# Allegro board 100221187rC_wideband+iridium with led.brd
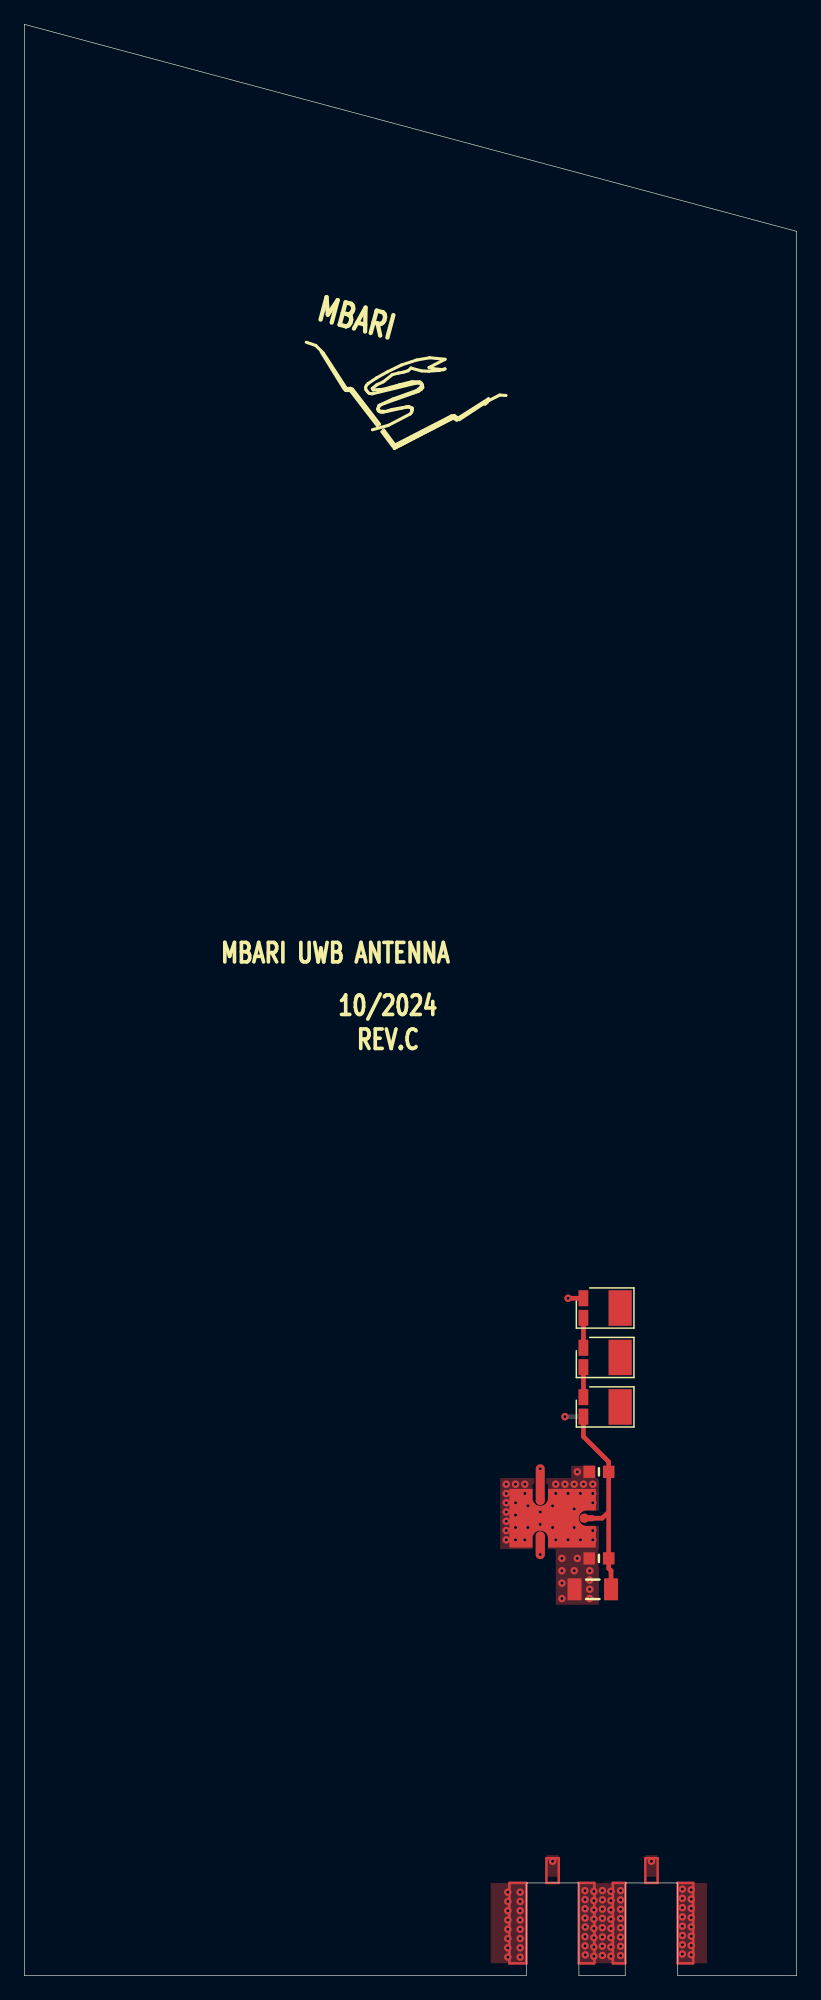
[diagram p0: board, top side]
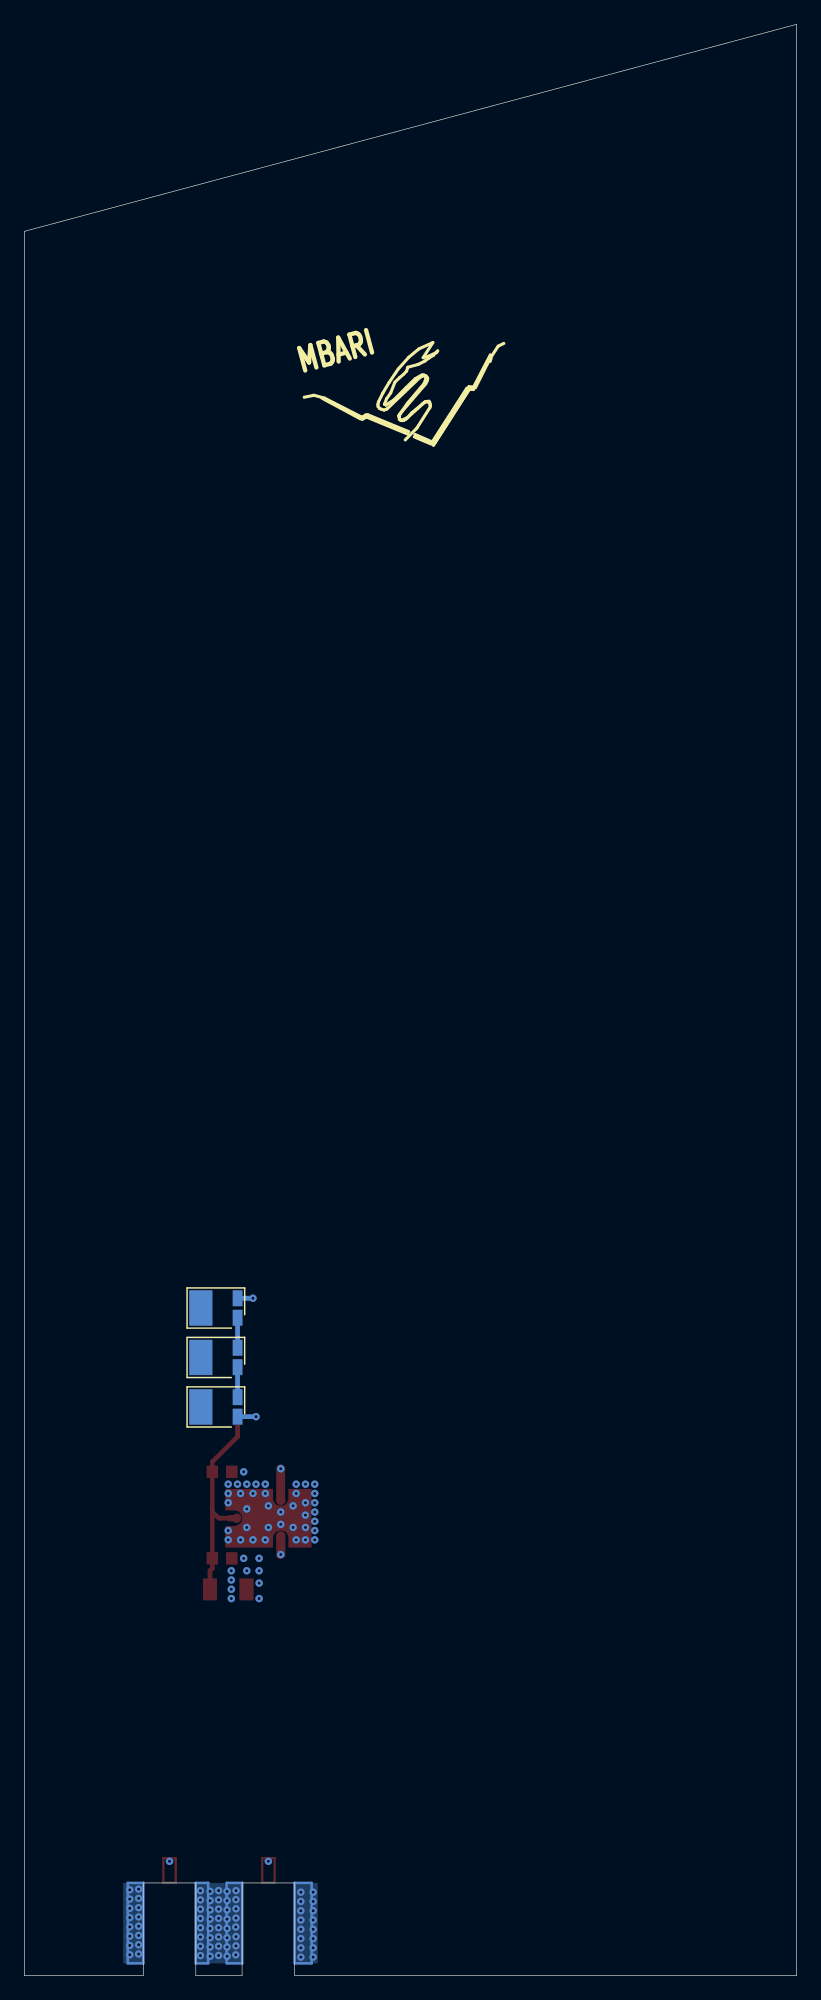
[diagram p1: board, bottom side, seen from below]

Outline 63.5 x 160.35 mm; copper layers: TOP, IN1, IN2, BOTTOM. Coordinates in mm from the lower left corner of the outline.
Outline path: 0,160.35 63.5,143.33 63.5,0 53.72,0 53.72,7.62 49.4,7.62 49.4,0 45.59,0 45.59,7.62 41.27,7.62 41.27,0 0,0 0,160.35

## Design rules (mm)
constraint set DEFAULT: min track width 0.127

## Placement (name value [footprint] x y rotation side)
C1  1.0uF  [CAPC3216X190N]  46.74 31.75 180 top
C2  10,000.0pF  [CAPC1608X87N]  47.24 41.4 180 top
C3  10,000.0pF  [CAPC1608X87N]  47.24 34.29 180 top
D1  LXM2-PH01-0070  [DIODFN449X305X210-3N]  47.75 46.74 0 top
D2  LXM2-PH01-0070  [DIODFN449X305X210-3N]  47.75 50.8 0 top
D3  LXM2-PH01-0070  [DIODFN449X305X210-3N]  47.75 54.86 0 top
D4  LXM2-PH01-0070  [DIODFN449X305X210-3N]  47.75 54.86 0 bottom
D5  LXM2-PH01-0070  [DIODFN449X305X210-3N]  47.75 50.8 0 bottom
D6  LXM2-PH01-0070  [DIODFN449X305X210-3N]  47.75 46.74 0 bottom
NOREF  -  []  -122.94 -69.6 0 top
NOREF#2  -  []  52.32 -0.64 0 top
NOREF#3  -  []  0 0 0 top
NOREF#4  -  []  41.27 0 0 top
NOREF#5  -  []  32.77 134.37 345 top
NOREF#6  -  []  -122.94 -69.6 0 top
NOREF#7  -  []  45.59 0 0 top
NOREF#8  -  []  79.76 11.43 0 top
NOREF#9  -  []  49.4 0 0 top
NOREF#10  -  []  63.5 0 90 top
NOREF#11  -  []  0 0 90 top
NOREF#12  -  []  0 160.35 0 top
NOREF#13  -  []  32.26 134.62 165 bottom
U1  BT-0014SMG  [MARKI_BTSM-PDSM]  43.43 37.59 0 top

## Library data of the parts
C1-C3 = CAP
D1-D6 = LED_C1A2
U1 = MARKI_BT-0014SMG-1

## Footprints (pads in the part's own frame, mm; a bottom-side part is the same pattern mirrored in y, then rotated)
CAPC1608X87N
  rect 0.95x1.001 smd: 1(-0.8,0) 2(0.8,0)
CAPC3216X190N
  rect 1.151x1.801 smd: 1(-1.501,0) 2(1.501,0)
DIODFN449X305X210-3N
  rect 1.89x2.901 smd: (1.234,0)
  rect 0.79x1.3 smd: 1(-1.786,0.8) 2(-1.786,-0.8)
MARKI_BTSM-PDSM
  custom 0.191x0.191 smd: 1(-1.016,-1.651) 2(-1.016,1.651) 3(2.794,0)
  custom 1.206x1.206 smd: 4(0,0)

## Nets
GND_SIGNAL: C1.2 C2.2 C3.2 D6.1(C) U1.4(GND)
LED: C1.1 C2.1 C3.1 D1.2 U1.3
UWB FEEDLINE: U1.2
N06909: U1.1
N07165: D1.1(C) D2.2
N048171: D2.1(C) D3.2
N048451: D3.1(C) D4.2
N048711: D4.1(C) D5.2
N048971: D5.1(C) D6.2

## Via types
v1: diameter 0.61, hole 0.254, TOP to BOTTOM, 127 vias
v2: diameter 0.61, hole 0.254, IN1 to IN2, 1 via

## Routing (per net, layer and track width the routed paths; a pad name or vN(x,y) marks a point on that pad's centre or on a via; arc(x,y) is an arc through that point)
GND_SIGNAL: length 103.8
  IN1 w1.092: 51.56,9.27 v1(51.56,9.4) 51.56,10.42 arc(51.78,14.95) 52.45,19.43 arc(53.21,24.55) 53.47,29.72 53.47,66.6 arc(52.12,71.06) 48.53,74.01 32.21,80.82 arc(29.41,83.47) 29.09,87.32 v2(31.75,96.77)
  BOTTOM w0.381: D6.1 v1(44.45,45.94)
  vias: v1(39.62,40.39) v1(39.62,39.62) v1(39.62,38.86) v1(39.62,38.1) v1(39.62,37.34) v1(39.62,36.58) v1(39.62,35.81) v1(39.75,6.86) v1(39.75,6.1) v1(39.75,5.33) v1(39.75,4.57) v1(39.75,3.81) v1(39.75,3.05) v1(39.75,2.29) v1(39.75,1.52) v1(40.39,40.39) v1(40.39,38.86) v1(40.39,37.85) v1(40.39,36.83) v1(40.39,35.81) v1(40.77,6.86) v1(40.77,6.1) v1(40.77,5.33) v1(40.77,4.57) v1(40.77,3.81) v1(40.77,3.05) v1(40.77,2.29) v1(40.77,1.52) v1(41.15,40.39) v1(41.15,39.62) v1(41.15,35.81) v1(41.4,38.61) v1(41.4,36.83) v1(42.42,38.1) v1(42.42,37.08) v1(43.43,38.61) v1(43.43,36.83) v1(43.69,40.39) v1(43.69,39.62) v1(43.69,35.81) v1(44.2,34.29) v1(44.2,33.27) v1(44.2,32.26) v1(44.2,30.99) v1(44.45,40.39) v1(44.7,39.62) v1(44.7,35.81) v1(45.21,40.39) v1(45.21,38.35) v1(45.21,36.83) v1(45.21,33.27) v1(45.47,41.4) v1(45.47,34.29) v1(45.72,39.62) v1(45.72,35.81) v1(45.97,40.39) v1(46.09,6.99) v1(46.1,6.25) v1(46.1,5.49) v1(46.1,4.73) v1(46.12,4) v1(46.1,3.21) v1(46.1,2.45) v1(46.12,1.71) v1(46.48,33.27) v1(46.48,32.51) v1(46.48,31.75) v1(46.48,30.99) v1(46.74,40.39) v1(46.74,39.62) v1(46.74,38.86) v1(46.74,36.58) v1(46.74,35.81) v1(46.83,6.93) v1(46.83,6.16) v1(46.83,5.4) v1(46.83,4.64) v1(46.83,3.88) v1(46.83,3.12) v1(46.83,2.35) v1(46.83,1.59) v1(47.53,6.99) v1(47.53,6.23) v1(47.53,5.47) v1(47.53,4.71) v1(47.53,3.94) v1(47.53,3.18) v1(47.53,2.42) v1(47.53,1.66) v1(48.23,6.93) v1(48.23,6.16) v1(48.23,5.4) v1(48.23,4.64) v1(48.23,3.88) v1(48.23,3.12) v1(48.23,2.35) v1(48.23,1.59) v1(49.02,6.99) v1(49.02,6.22) v1(49.02,5.46) v1(49.02,4.7) v1(49.02,3.94) v1(49.02,3.17) v1(49.02,2.41) v1(49.02,1.65) v1(54.1,7.11) v1(54.1,6.35) v1(54.1,5.59) v1(54.1,4.83) v1(54.1,4.06) v1(54.1,3.3) v1(54.1,2.54) v1(54.1,1.78) v1(54.83,7.05) v1(54.83,6.29) v1(54.83,5.53) v1(54.83,4.77) v1(54.83,4.01) v1(54.83,3.24) v1(54.83,2.48) v1(54.83,1.72)
LED: length 17.1
  TOP w0.381: 48.04,38.04 47.99,38.04 47.5,37.59 U1.3 ; 48.04,38.04 C3.1 48.04,33.47 48.24,33.28 C1.1 ; 48.04,38.04 C2.1 48.04,42.22 45.97,44.3 D1.2
UWB FEEDLINE: length 73.1
  TOP w0.737: U1.2 v1(42.42,41.66)
  IN1 w1.092: 22.35,103.12 18.41,88.23 arc(18.44,76.33) 24.39,66.03 37.93,52.5 arc(41.25,47.53) 42.42,41.66
N06909: length 26.6
  TOP w0.762: U1.1 v1(42.42,34.61)
  IN1 w1.092: v1(42.42,34.61) 42.42,29.26 arc(42.51,25.23) 42.8,21.21 arc(43.2,16.1) 43.43,10.97 v1(43.43,9.4)
N07165: length 2.5
  TOP w0.381: D2.2 D1.1
N048171: length 2.5
  TOP w0.381: D3.2 D2.1
N048451: length 2.5
  TOP w0.381: v1(44.7,55.66) D3.1
  BOTTOM w0.381: D3.1 v1(44.7,55.66)
N048711: length 2.5
  BOTTOM w0.381: D4.1 D5.2
N048971: length 2.5
  BOTTOM w0.381: D5.1 D6.2

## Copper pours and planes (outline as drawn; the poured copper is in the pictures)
GND_SIGNAL on TOP: 41.27,1.02 41.27,7.62 38.35,7.62 38.35,1.02
GND_SIGNAL on TOP: 52.07,8.13 51.05,8.13 51.05,9.91 52.07,9.91
GND_SIGNAL on TOP: 53.72,7.62 53.72,1.02 56.13,1.02 56.13,7.62
GND_SIGNAL on TOP: 43.69,30.48 43.69,35.05 39.12,35.05 39.12,40.89 44.96,40.89 44.96,41.91 46.99,41.91 46.99,40.89 47.24,40.89 47.24,30.48
GND_SIGNAL on TOP: 45.59,7.62 45.59,1.02 49.4,1.02 49.4,7.62
GND_SIGNAL on BOTTOM: 39.37,7.62 39.37,1.02 41.27,1.02 41.27,7.62
GND_SIGNAL on BOTTOM: 45.59,1.02 45.59,7.62 49.4,7.62 49.4,1.02
GND_SIGNAL on BOTTOM: 53.72,7.62 53.72,1.02 55.37,1.02 55.37,7.62
GND_SIGNAL on IN2: 55.95,83.82 56.33,83.82 56.39,1.31 56.39,1.02 53.72,1.02 53.72,7.62 49.4,7.62 49.4,1.02 45.59,1.02 45.59,7.62 41.27,7.62 41.27,1.02 7.37,1.02 7.37,14.58 7.37,14.58 7.37,106.75 23.63,102.39 23.45,101.72 56.53,92.86 55.68,89.67 25.62,97.72 24.17,92.33 55.95,83.81 ; 2 cut-outs
UWB FEEDLINE on IN1: 55.85,131.03 7.42,144.01 22.29,102.66
N06909 on TOP: 43.94,8.13 42.93,8.13 42.93,9.91 43.94,9.91

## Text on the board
User.Comments: rev B | Origin | REV C: D.THOMPSON
Ref Des/Silkscreen Top: MBARI UWB ANTENNA | 10/2024 | REV.C
XSECTION_CHART: *  PLATING: ENIG | L1: TOP CONDUCTOR - COPPER 2.1 MIL | *  DIELECTRIC - 4003C 32 mil | L2: IN1 CONDUCTOR - COPPER 1.4 MIL | *  DIELECTRIC - 4003C 20 mil | L3: IN2 CONDUCTOR - COPPER 1.4 MIL | L4: BOTTOM CONDUCTOR - COPPER 2.1 MIL | DESIGN CROSS SECTION CHART | ___________________________ | TOTAL THICKNESS 93 MIL | 1-4 | 2-3
PAGE_OUTLINE: WIDEN CABLE INPUT SLOTS | ENLARGE OUTLINE, | c
DIMENSION: (2x) ADD EDGE PLATING INSIDE | BOTH SLOTS.
PLACE_BOUND_TOP: FIGURE | FINISHED_SIZE | 10.0 | DRILL CHART: TOP to BOTTOM | ALL UNITS ARE IN MILS | DRILLED_SIZE | - | PLATED | QTY | 127
User.10: FIGURE | FINISHED_SIZE | 10.0 | DRILL CHART: IN1 to IN2 | ALL UNITS ARE IN MILS | DRILLED_SIZE | - | PLATED | QTY | 1
